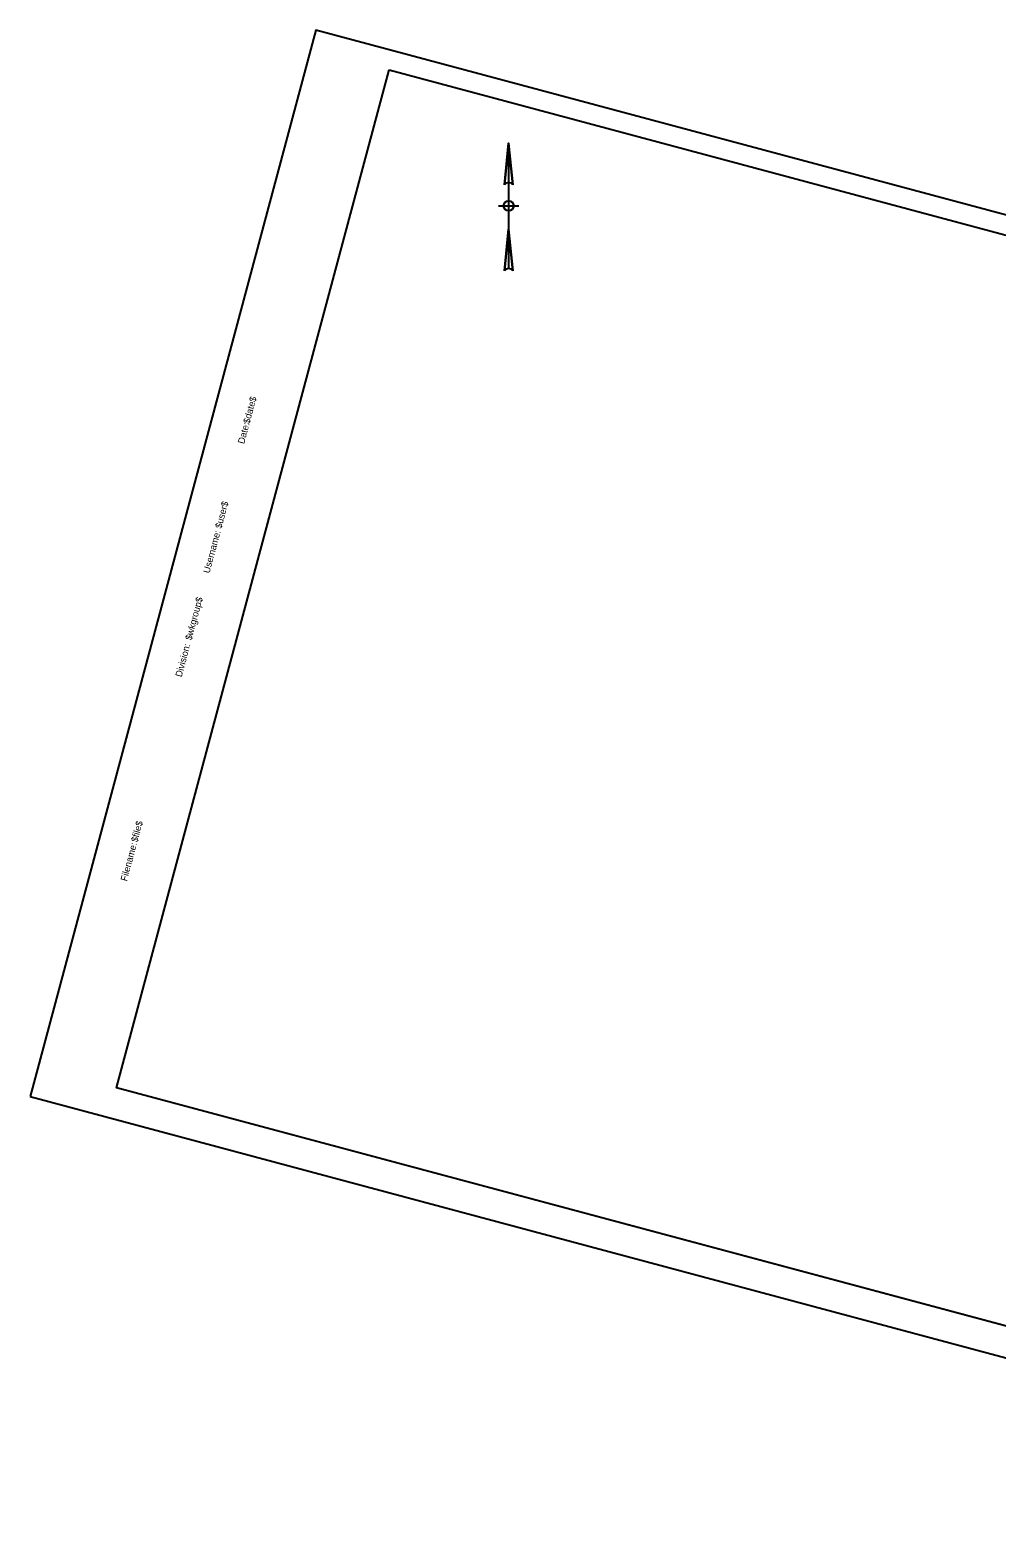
# Model space of a CAD drawing. Extents: x 1761761 to 1762725, y 480915 to 481666.
# Drawn here: x 1761761 to 1762243, y 480915 to 481666 of the extents above; entities that cross this region are included whole.
import ezdxf

# ---------------------------------------------------------------- set-up
doc = ezdxf.new("R2010")
doc.units = 0
for name, color, linetype in [('BORDER', 7, 'Continuous'), ('CLIPS', 7, 'Continuous'), ('H_V CONTROLS', 7, 'Continuous'), ('PLOT BOUNDARY', 7, 'Continuous')]:
    doc.layers.add(name, color=color, linetype=linetype)

msp = doc.modelspace()

# ---------------------------------------------------------------- linework, layer by layer
at = {"layer": 'BORDER'}
msp.add_lwpolyline([(1761940.25, 481646.06), (1762712.99, 481439), (1762577.11, 480931.89), (1761804.37, 481138.94)], close=True, dxfattribs=at)
at = {"layer": 'CLIPS'}
msp.add_lwpolyline([(1761940.25, 481646.06), (1762664.7, 481451.94), (1762528.82, 480944.83), (1761804.37, 481138.94)], close=True, dxfattribs=at)
at = {"layer": 'H_V CONTROLS'}
for p, q in [((1761997.67, 481588.76), (1761999.76, 481609.6)), ((1761999.76, 481609.6), (1761999.76, 481547.1)), ((1761999.76, 481609.6), (1762001.84, 481588.76)), ((1761994.76, 481578.35), (1762004.76, 481578.35)), ((1761997.67, 481545.98), (1761999.76, 481566.81)), ((1761999.76, 481566.81), (1762001.84, 481545.98))]:
    msp.add_line(p, q, dxfattribs=at)
for points in [[(1762001.84, 481588.76), (1761999.76, 481609.6), (1761998.72, 481599.18), (1761997.67, 481588.76)], [(1762001.84, 481545.98), (1761999.76, 481566.81), (1761998.72, 481556.4), (1761997.67, 481545.98)]]:
    msp.add_lwpolyline(points, dxfattribs=at)
msp.add_circle((1761999.76, 481578.35), 2.5, dxfattribs=at)
for centre in [(1761999.76, 481587.38), (1761999.76, 481587.38), (1761999.76, 481544.6), (1761999.76, 481544.6)]:
    msp.add_arc(centre, 2.5, 33.55731, 146.44269, dxfattribs=at)
at = {"layer": 'PLOT BOUNDARY'}
msp.add_lwpolyline([(1761761.33, 481134.64), (1762582.36, 480914.65), (1762724.71, 481445.91), (1761903.68, 481665.9)], close=True, dxfattribs=at)

# ---------------------------------------------------------------- texts
at = {"layer": 'BORDER'}
for s, p in [('$date$', (1761870.63, 481469.59)), ('Date:', (1761867.93, 481459.5)), ('$user$', (1761856.64, 481417.36)), ('Username:', (1761850.66, 481395.03)), ('$wkgroup$', (1761841.73, 481361.71)), ('Division:', (1761836.81, 481343.35)), ('$file$', (1761814.75, 481261.05)), ('Filename:', (1761809.54, 481241.6))]:
    msp.add_text(s, height=3.348, rotation=75, dxfattribs=at).set_placement(p)

doc.saveas('drawing.dxf')
